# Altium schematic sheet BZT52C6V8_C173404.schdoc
size 127 x 101 mm
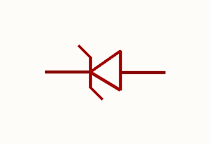
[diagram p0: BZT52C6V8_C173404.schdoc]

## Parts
D?  bzt52c6v8_c173404  [SOD-123_L2.8-W1.8-LS3.7-RD]  (value not drawn)

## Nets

Not connected (* = marked no-connect by the designer): D? 1 2

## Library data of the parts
D? = bzt52c6v8_c173404: 二极管配置:1个独立式;稳压值(标称值):6.8V;稳压值(范围):6.46V~7.14V;耗散功率(Pd):500mW;; Manufacturer: MDD(辰达半导体); AddInBom: yes; ModelId: 7884390a25fb4c08947731ebfba7e3f8; ModelTransform: 144.8816,62.992,0,0,0,0,0,0,0; Diode Configuration: 1个独立式; Zener Voltage(Nom): 6.8V; Reverse Leakage Current (Ir): 500nA@3.5V; Pd - Power Dissipation: 500mW; Impedance(Zzt): 30Ω; Tolerance: ±5%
